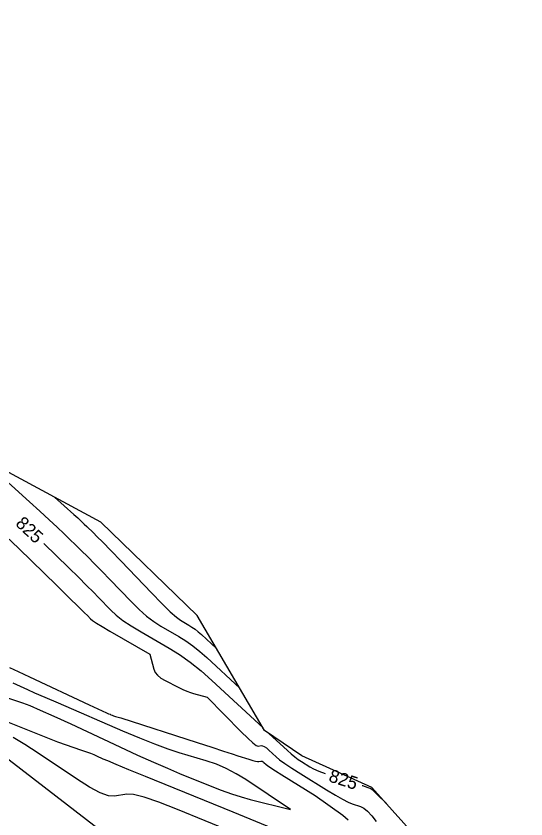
# Model space of a CAD drawing. Extents: x 1715724 to 1716561, y 394063 to 395906.
# Drawn here: x 1716427 to 1716482.3, y 394587.6 to 394674.6 of the extents above; entities that cross this region are included whole.
import ezdxf

# ---------------------------------------------------------------- set-up
doc = ezdxf.new("R2010")
doc.units = 0
for name, color, linetype in [('DT_X_Contour_Major', 7, 'Continuous'), ('DT_X_Contour_Minor', 7, 'Continuous'), ('DT_X_TIN_Hull', 7, 'Continuous')]:
    doc.layers.add(name, color=color, linetype=linetype)

msp = doc.modelspace()

# ---------------------------------------------------------------- linework, layer by layer
at = {"layer": 'DT_X_Contour_Major'}
for points in [[(1716429.978, 394617.488), (1716432.711, 394614.829), (1716433.748, 394613.815), (1716434.631, 394612.944), (1716435.36, 394612.215), (1716435.934, 394611.628), (1716437.258, 394610.253), (1716437.835, 394609.72), (1716438.572, 394609.151), (1716439.471, 394608.546), (1716440.53, 394607.906), (1716443.568, 394606.15), (1716444.713, 394605.437), (1716445.871, 394604.613), (1716447.04, 394603.679), (1716448.222, 394602.634), (1716453.766, 394597.502)], [(1716454.402, 394596.906), (1716456.392, 394595.067), (1716456.807, 394594.696), (1716457.201, 394594.371), (1716457.574, 394594.091), (1716457.925, 394593.857), (1716458.832, 394593.294), (1716459.242, 394593.073), (1716459.794, 394592.832), (1716460.486, 394592.572), (1716460.503, 394592.566)], [(1716464.496, 394591.266), (1716464.523, 394591.257), (1716465.099, 394591.059), (1716465.458, 394590.923), (1716465.598, 394590.848), (1716465.681, 394590.732), (1716465.734, 394590.669), (1716465.832, 394590.566), (1716465.973, 394590.424), (1716466.159, 394590.242), (1716467.129, 394589.302)]]:
    msp.add_lwpolyline(points, dxfattribs=at)
at = {"layer": 'DT_X_Contour_Minor'}
for points in [[(1716422.93, 394626.919), (1716428.454, 394621.975), (1716429.576, 394620.964), (1716430.575, 394620.051), (1716431.449, 394619.235), (1716432.199, 394618.516), (1716434.035, 394616.73), (1716434.746, 394616.031), (1716435.501, 394615.275), (1716436.302, 394614.461), (1716437.147, 394613.588), (1716439.461, 394611.186), (1716440.313, 394610.344), (1716441.132, 394609.621), (1716441.918, 394609.017), (1716442.672, 394608.532), (1716444.638, 394607.395), (1716445.38, 394606.933), (1716446.129, 394606.4), (1716446.886, 394605.795), (1716447.651, 394605.119), (1716451.24, 394601.797)], [(1716431.132, 394622.509), (1716433.235, 394620.627), (1716433.662, 394620.243), (1716434.042, 394619.895), (1716434.375, 394619.584), (1716434.66, 394619.311), (1716435.359, 394618.631), (1716435.743, 394618.247), (1716436.371, 394617.606), (1716437.244, 394616.706), (1716438.361, 394615.549), (1716441.664, 394612.119), (1716442.79, 394610.969), (1716443.691, 394610.092), (1716444.365, 394609.488), (1716444.814, 394609.158), (1716445.709, 394608.641), (1716446.047, 394608.43), (1716446.388, 394608.187), (1716446.732, 394607.912), (1716447.081, 394607.604), (1716448.714, 394606.092)], [(1716425.885, 394618.278), (1716427.277, 394616.927), (1716431.387, 394612.928), (1716432.751, 394611.6), (1716433.761, 394610.613), (1716434.418, 394609.97), (1716434.72, 394609.668), (1716435.055, 394609.321), (1716435.28, 394609.14), (1716435.706, 394608.858), (1716436.333, 394608.474), (1716437.159, 394607.989), (1716441.484, 394605.49), (1716441.913, 394603.857), (1716442.06, 394603.518), (1716442.315, 394603.2), (1716442.679, 394602.903), (1716443.151, 394602.627), (1716444.557, 394601.921), (1716445.057, 394601.679), (1716445.503, 394601.481), (1716445.895, 394601.329), (1716446.233, 394601.221), (1716447.685, 394600.822), (1716451.397, 394597.079), (1716452.108, 394596.38), (1716452.651, 394595.888), (1716453.025, 394595.602), (1716453.232, 394595.523), (1716453.558, 394595.587), (1716453.701, 394595.574), (1716453.887, 394595.488), (1716454.116, 394595.328), (1716454.387, 394595.095), (1716455.166, 394594.375), (1716455.553, 394594.057), (1716456.129, 394593.644), (1716456.893, 394593.136), (1716457.847, 394592.533), (1716460.642, 394590.799), (1716461.602, 394590.216), (1716462.385, 394589.768), (1716462.991, 394589.456), (1716463.421, 394589.279), (1716464.33, 394588.987), (1716464.691, 394588.802), (1716465.095, 394588.468), (1716465.539, 394587.983), (1716466.026, 394587.349)], [(1716426.272, 394604.044), (1716427.215, 394603.611), (1716428.449, 394603.032), (1716434.89, 394599.991), (1716436.778, 394599.149), (1716437.01, 394599.045), (1716437.17, 394598.975), (1716437.258, 394598.936), (1716437.397, 394598.876), (1716437.458, 394598.852), (1716437.538, 394598.824), (1716437.636, 394598.792), (1716437.752, 394598.756), (1716438.336, 394598.581), (1716446.601, 394595.916), (1716448.206, 394595.399), (1716449.481, 394594.989), (1716450.425, 394594.686), (1716451.038, 394594.49), (1716452.232, 394594.111), (1716452.634, 394593.989), (1716452.944, 394593.906), (1716453.163, 394593.863), (1716453.29, 394593.859), (1716453.506, 394593.902), (1716453.588, 394593.905), (1716453.672, 394593.885), (1716453.758, 394593.84), (1716453.845, 394593.77), (1716454.08, 394593.553), (1716454.254, 394593.421), (1716454.6, 394593.191), (1716455.116, 394592.86), (1716455.803, 394592.43), (1716459.412, 394590.191), (1716462.404, 394588.038), (1716462.995, 394587.562)], [(1716426.057, 394600.77), (1716427.681, 394600.219), (1716428.464, 394599.921), (1716429.596, 394599.442), (1716431.075, 394598.78), (1716432.903, 394597.936), (1716438.242, 394595.443), (1716440.148, 394594.562), (1716441.863, 394593.789), (1716443.386, 394593.124), (1716444.717, 394592.568), (1716448.012, 394591.228), (1716449.21, 394590.759), (1716450.333, 394590.358), (1716451.382, 394590.024), (1716452.356, 394589.758), (1716456.727, 394588.673), (1716451.879, 394591.897), (1716450.833, 394592.543), (1716449.77, 394593.099), (1716448.693, 394593.564), (1716447.599, 394593.939), (1716444.662, 394594.819), (1716443.455, 394595.213), (1716442.036, 394595.734), (1716440.405, 394596.383), (1716438.563, 394597.16), (1716431.586, 394600.17), (1716430.141, 394600.797), (1716429.033, 394601.28), (1716428.261, 394601.621), (1716426.65, 394602.34)], [(1716455.421, 394586.364), (1716450.521, 394588.374), (1716441.02, 394592.238), (1716439.206, 394592.978), (1716437.837, 394593.54), (1716436.914, 394593.926), (1716436.435, 394594.134), (1716435.752, 394594.453), (1716435.457, 394594.582), (1716435.087, 394594.728), (1716434.641, 394594.891), (1716434.12, 394595.072), (1716431.508, 394595.959), (1716424.975, 394598.541)], [(1716450.486, 394586.21), (1716444.488, 394588.671), (1716442.457, 394589.467), (1716440.863, 394590.01), (1716439.706, 394590.299), (1716438.985, 394590.336), (1716437.647, 394590.095), (1716437.013, 394590.146), (1716436.115, 394590.479), (1716434.955, 394591.094), (1716433.531, 394591.992), (1716429.382, 394594.762), (1716427.921, 394595.71), (1716426.65, 394596.477)]]:
    msp.add_lwpolyline(points, dxfattribs=at)
at = {"layer": 'DT_X_TIN_Hull'}
for points in [[(1716482.258, 394572.447), (1716465.562, 394591.047), (1716457.962, 394594.493), (1716453.927, 394597.228), (1716446.604, 394609.681), (1716436.172, 394619.799), (1716418.865, 394629.105), (1716416.186, 394631.116), (1716416.371, 394639.039), (1716409.961, 394644.585), (1716402.736, 394643.917), (1716385.852, 394656.318), (1716374.782, 394668.715), (1716365.574, 394674.608)], [(1716362.292, 394649.196), (1716385.754, 394645.713), (1716396.521, 394623.151), (1716401.227, 394622.862), (1716411.356, 394620.263), (1716410.244, 394616.644), (1716410.559, 394606.887), (1716420.351, 394598.572), (1716437.143, 394585.644)]]:
    msp.add_lwpolyline(points, dxfattribs=at)

# ---------------------------------------------------------------- texts
at = {"layer": 'DT_X_Contour_Major'}
for rotation, p in [(316.49114, (1716426.836, 394619.526)), (341.96425, (1716460.777, 394591.736))]:
    msp.add_text('825', height=1.4, rotation=rotation, dxfattribs=at).set_placement(p)

doc.saveas('drawing.dxf')
